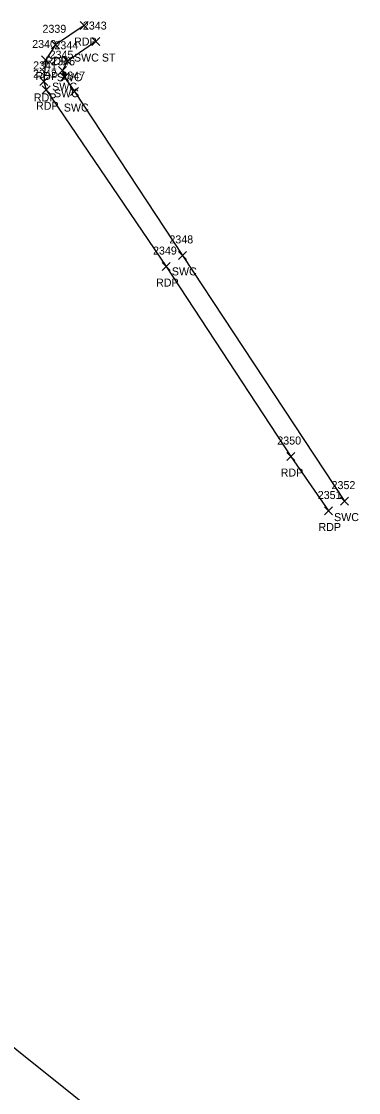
# Model space of a CAD drawing. Extents: x 1635588 to 1637550, y 621583 to 623638.
# Drawn here: x 1637166 to 1637250.3, y 621810.1 to 622077.8 of the extents above; entities that cross this region are included whole.
import ezdxf

# ---------------------------------------------------------------- set-up
doc = ezdxf.new("R2010")
doc.units = 0
for name, color, linetype in [('LBC', 7, 'Continuous'), ('P_A', 7, 'Continuous'), ('P_I', 7, 'Continuous'), ('P_TIC', 7, 'Continuous'), ('PET', 7, 'Continuous'), ('R_A', 7, 'Continuous'), ('R_I', 7, 'Continuous'), ('R_TIC', 7, 'Continuous'), ('RSW', 7, 'Continuous')]:
    doc.layers.add(name, color=color, linetype=linetype)

msp = doc.modelspace()

# ---------------------------------------------------------------- linework, layer by layer
at = {"layer": 'LBC'}
msp.add_lwpolyline([(1637127.75, 621845.35), (1637128.26, 621844.95), (1637131.72, 621847.95), (1637150.11, 621832.58), (1637193.82, 621797.61), (1637199.24, 621804.01)], dxfattribs=at)
at = {"layer": 'P_TIC'}
for points in [[(1637180.7, 622075.82), (1637182.7, 622077.82)], [(1637182.7, 622075.82), (1637180.7, 622077.82)], [(1637173.57, 622071), (1637175.57, 622073)], [(1637175.57, 622071), (1637173.57, 622073)], [(1637171.09, 622067.2), (1637173.09, 622069.2)], [(1637173.09, 622067.2), (1637171.09, 622069.2)], [(1637170.66, 622061.85), (1637172.66, 622063.85)], [(1637172.66, 622061.85), (1637170.66, 622063.85)], [(1637171.19, 622059.76), (1637173.19, 622061.76)], [(1637173.19, 622059.76), (1637171.19, 622061.76)], [(1637201.21, 622015.57), (1637203.21, 622017.57)], [(1637203.21, 622015.57), (1637201.21, 622017.57)], [(1637232.36, 621968.09), (1637234.36, 621970.09)], [(1637234.36, 621968.09), (1637232.36, 621970.09)], [(1637241.83, 621954.48), (1637243.83, 621956.48)], [(1637243.83, 621954.48), (1637241.83, 621956.48)]]:
    msp.add_lwpolyline(points, dxfattribs=at)
at = {"layer": 'PET'}
msp.add_lwpolyline([(1637181.7, 622076.82), (1637174.57, 622072), (1637172.09, 622068.2), (1637171.66, 622062.85), (1637172.19, 622060.76), (1637202.21, 622016.57), (1637233.36, 621969.09), (1637242.83, 621955.48)], dxfattribs=at)
at = {"layer": 'R_TIC'}
for points in [[(1637183.67, 622071.81), (1637185.67, 622073.81)], [(1637185.67, 622071.81), (1637183.67, 622073.81)], [(1637176.54, 622066.88), (1637178.54, 622068.88)], [(1637178.54, 622066.88), (1637176.54, 622068.88)], [(1637175.35, 622064.54), (1637177.35, 622066.54)], [(1637177.35, 622064.54), (1637175.35, 622066.54)], [(1637175.82, 622062.89), (1637177.82, 622064.89)], [(1637177.82, 622062.89), (1637175.82, 622064.89)], [(1637178.28, 622059.31), (1637180.28, 622061.31)], [(1637180.28, 622059.31), (1637178.28, 622061.31)], [(1637205.29, 622018.36), (1637207.29, 622020.36)], [(1637207.29, 622018.36), (1637205.29, 622020.36)], [(1637245.84, 621956.95), (1637247.84, 621958.95)], [(1637247.84, 621956.95), (1637245.84, 621958.95)]]:
    msp.add_lwpolyline(points, dxfattribs=at)
at = {"layer": 'RSW'}
msp.add_lwpolyline([(1637184.67, 622072.81), (1637177.54, 622067.88), (1637176.35, 622065.54), (1637176.82, 622063.89), (1637179.28, 622060.31), (1637206.29, 622019.36), (1637246.84, 621957.95)], dxfattribs=at)

# ---------------------------------------------------------------- texts
at = {"layer": 'P_A'}
for p in [(1637179.19, 622071.82), (1637172.06, 622067), (1637169.57, 622063.2), (1637169.15, 622057.85), (1637169.68, 622055.76), (1637199.7, 622011.57), (1637230.85, 621964.09), (1637240.31, 621950.48)]:
    msp.add_text('RDP', height=2, dxfattribs=at).set_placement(p)
at = {"layer": 'P_I'}
for s, p in [('2339', (1637171.3, 622075)), ('2340', (1637168.74, 622071.2)), ('2341', (1637168.97, 622065.85)), ('2342', (1637168.93, 622063.76)), ('2349', (1637198.94, 622019.57)), ('2350', (1637230.01, 621972.09)), ('2351', (1637240.13, 621958.48))]:
    msp.add_text(s, height=2, dxfattribs=at).set_placement(p)
at = {"layer": 'R_A'}
for s, p in [('SWC ST', (1637179.17, 622067.81)), ('SWC', (1637173.71, 622060.54)), ('SWC', (1637174.91, 622062.88)), ('SWC', (1637174.18, 622058.89)), ('SWC', (1637176.64, 622055.31)), ('SWC', (1637203.65, 622014.36)), ('SWC', (1637244.2, 621952.95))]:
    msp.add_text(s, height=2, dxfattribs=at).set_placement(p)
at = {"layer": 'R_I'}
for s, p in [('2343', (1637181.41, 622075.81)), ('2345', (1637173.09, 622068.54)), ('2344', (1637174.28, 622070.88)), ('2346', (1637173.5, 622066.89)), ('2347', (1637176.02, 622063.31)), ('2348', (1637203.03, 622022.36)), ('2352', (1637243.58, 621960.95))]:
    msp.add_text(s, height=2, dxfattribs=at).set_placement(p)

doc.saveas('drawing.dxf')
